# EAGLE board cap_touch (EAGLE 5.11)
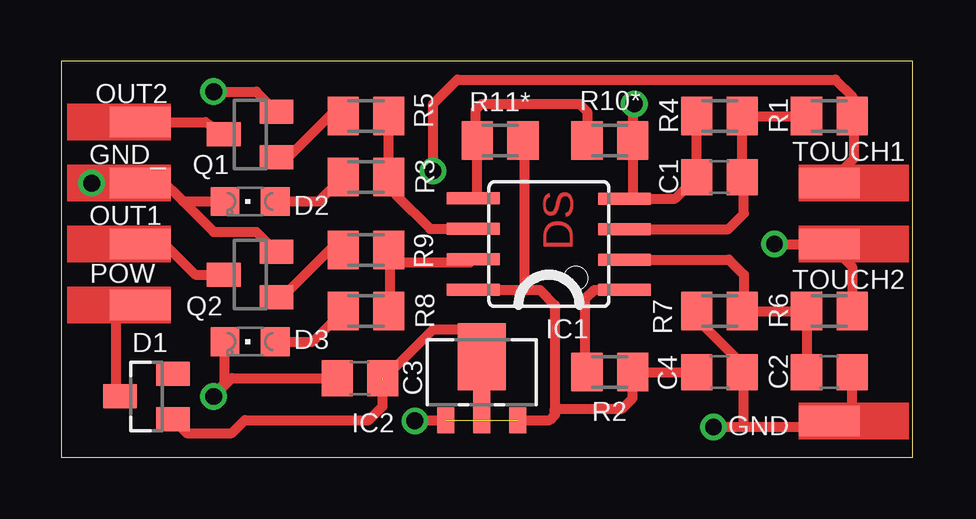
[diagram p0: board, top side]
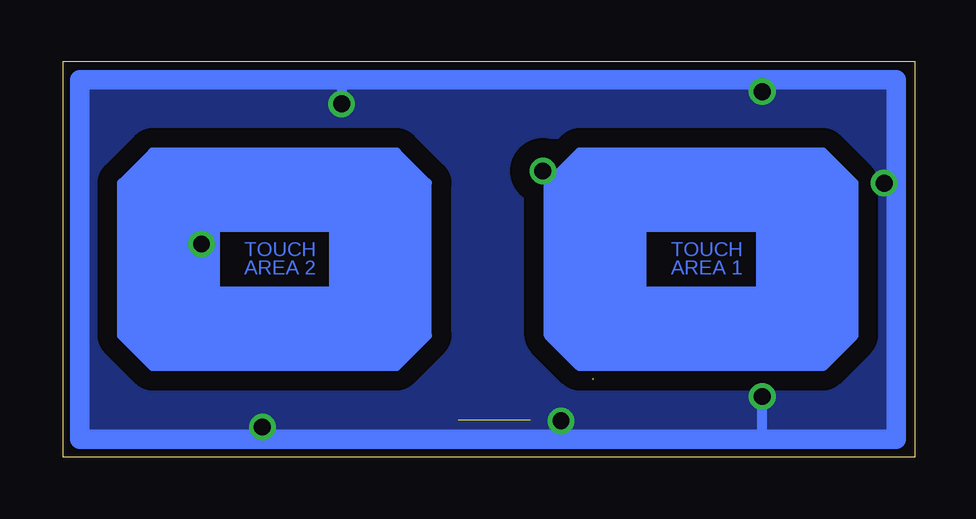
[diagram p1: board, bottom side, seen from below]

Size 35.48 x 16.5 mm. Coordinates in mm from the lower left corner, seen from the top.
Outline: 0,0 35.48,0 35.48,16.5 0,16.5 0,0
Copper layers (1*16): Top 0.035mm / dielectric 1.5mm / Bottom 0.035mm
Design rules "default": minimum track width 10mil, minimum drill 24mil, track to track 8mil, track to pad 8mil, pad to pad 8mil, via to via 8mil, smd to smd 8mil, copper to edge 40mil, drill to drill 8mil, minimum pad ring 10mil, minimum via ring 8mil, stop-mask expansion 4mil, vias tented up to drill 0mil, thermal gap 10mil

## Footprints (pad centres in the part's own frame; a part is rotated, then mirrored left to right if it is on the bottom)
C0805 = smd 1.3 x 1.5: 1 -0.95,0; 2 0.95,0
SOT23 = smd 1 x 1.4: 1 -0.95,-1.1; 2 0.95,-1.1; 3 0,1.1
CHIPLED_0805 = smd 1.2 x 1.2: A 0,-1.05; C 0,1.05
SMD1,27-2,54 = smd 1.27 x 2.54: 1 0,0
SOIC8 = smd 0.5 x 2.2: 1 -1.905,-3.154; 2 -0.645,-3.154; 3 0.625,-3.154; 4 1.895,-3.154; 5 1.905,3.154; 6 0.635,3.154; 7 -0.635,3.154; 8 -1.905,3.154
SOT89R = smd 0.7 x 1.1: 1 1.5,-1.75; 2 -1.5,-1.75 | smd 0.7 x 1.8: 3 0,-1.4 | smd 2 x 2.8: 4 0,0.9
M0805 = smd 1.3 x 1.6: 1 -0.95,0; 2 0.95,0

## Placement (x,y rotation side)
C1  22p  [C0805]  27.43,11.68 180 top
C2  22p  [C0805]  32,3.56 180 top
C3  100n  [C0805]  12.45,3.3 180 top
C4  100n  [C0805]  27.43,3.56 0 top
D1  [SOT23]  3.56,2.54 90 top
D2  [CHIPLED_0805]  7.87,10.67 90 top
D3  [CHIPLED_0805]  7.87,4.83 90 top
GND  [SMD1,27-2,54]  32,1.52 90 top
GND_  [SMD1,27-2,54]  3.3,11.43 90 top
IC1  ATTINY45  [SOIC8]  20.32,8.89 90 top
IC2  [SOT89R]  17.53,3.3 0 top
OUT1  [SMD1,27-2,54]  3.3,8.89 90 top
OUT2  [SMD1,27-2,54]  3.3,13.97 270 top
POW  [SMD1,27-2,54]  3.3,6.35 90 top
Q1  [SOT23]  7.87,13.46 90 top
Q2  [SOT23]  7.87,7.62 90 top
R1  4k7  [M0805]  32,14.22 180 top
R2  120k  [M0805]  22.86,3.56 0 top
R3  1k  [M0805]  12.7,14.22 180 top
R4  120k  [M0805]  27.43,14.22 180 top
R5  1k  [M0805]  12.7,11.68 0 top
R6  4k7  [M0805]  32,6.1 180 top
R7  120k  [M0805]  27.43,6.1 180 top
R8  1l  [M0805]  12.7,8.64 180 top
R9  1k  [M0805]  12.7,6.1 0 top
R10*  4k7  [M0805]  22.86,13.21 0 top
R11*  4k7  [M0805]  18.29,13.21 180 top
TOUCH1  [SMD1,27-2,54]  32,11.43 90 top
TOUCH2  [SMD1,27-2,54]  32,8.89 90 top

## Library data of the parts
C1-C4 R1-R9 R10* R11* = rcl
D1 = diode
D2 D3 = led
GND GND_ OUT1 OUT2 POW TOUCH1 TOUCH2 = wirepad
IC1 = avr-4
IC2 = v-reg
Q1 Q2 = transistor-small-signal

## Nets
CAP1: R6.1 TOUCH2.1
CAP2: R1.1 TOUCH1.1
GND: C1.2 C2.1 C3.2 C4.2 D2.C D3.C GND.1 GND_.1 IC1.4 IC2.1 IC2.2 Q1.2 Q2.2 R4.2 R7.2 R10*.2
N$1: Q1.1 R3.2
N$2: IC1.1 R2.1
N$3: Q2.1 R8.2
N$4: D2.A R5.1
N$5: C1.1 IC1.3 R1.2 R4.1
N$6: C2.2 IC1.2 R6.2 R7.1
N$10: D3.A R9.1
N$12: OUT1.1 Q2.3
N$14: IC1.5 R10*.1 R11*.2
N$15: D1.3 POW.1
N$16: OUT2.1 Q1.3
N$18: C3.1 D1.1 IC2.3
SO1: IC1.7 R8.1 R9.2
SO2: IC1.6 R3.1 R5.2
VCC: C4.1 IC1.8 R2.2 R11*.1

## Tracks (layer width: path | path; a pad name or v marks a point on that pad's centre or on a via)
CAP1  (via drill 0.7)
  Top 0.406: R6.1 32.95,7.94 TOUCH2.1 v29.72,8.89
  Bottom 0.406: 33.02,8.89 33.02,5.08 31.75,3.81 21.59,3.81 20.32,5.08 20.32,11.43 21.59,12.7 31.75,12.7 33.02,11.43 33.02,8.89 | 33.02,8.89 v29.72,8.89
CAP2  (via drill 0.7)
  Top 0.406: v15.49,11.94 15.49,14.73 16.51,15.75 32.26,15.75 32.95,15.05 R1.1 33.02,14.16 33.02,12.45 TOUCH1.1
  Bottom 0.406: 15.24,11.43 v15.49,11.94 | 15.24,11.43 13.97,12.7 3.81,12.7 2.54,11.43 2.54,5.08 3.81,3.81 13.97,3.81 15.24,5.08 15.24,11.43
GND  (via drill 0.7)  (1 unrouted)
  Top 0.406: R4.2 C1.2 25.58,10.79 IC1.4 23.81,10.87 R10*.2 23.81,14.67 v23.88,14.73 | C2.1 32.95,1.97 32.26,1.27 32,1.27 | 28.45,1.27 32,1.27 | R7.2 26.48,5.78 28.38,3.88 C4.2 28.45,3.49 28.45,1.27 | 32,1.27 GND.1 | Q2.2 8.96,8.57 8.13,9.4 6.35,9.4 5.08,10.67 | 5.08,10.67 4.06,11.68 3.56,11.68 GND_.1 v1.27,11.43 | 5.08,10.67 D2.C | C3.2 7.11,3.3 v6.35,2.54 6.82,3.08 D3.C | Q1.2 8.96,14.41 8.13,15.24 v6.35,15.24 | v27.18,1.27 28.45,1.27 | IC2.2 14.76,1.55 v14.73,1.52 | IC2.1 20.35,1.55 20.57,1.78 20.57,2.03
  Bottom 0.406: 0.76,11.43 v1.27,11.43 | 6.35,15.75 v6.35,15.24 | 27.18,0.76 v27.18,1.27 | 6.35,0.76 v6.35,2.54 | 23.88,15.75 v23.88,14.73 | 14.73,0.76 v14.73,1.52
  Bottom 0.813: 0.76,11.43 0.76,15.75 6.35,15.75 23.88,15.75 34.8,15.75 34.8,0.76 27.18,0.76 14.73,0.76 6.35,0.76 0.76,0.76 0.76,11.43
  pour Bottom (isolate 0.813, no thermals): 0.51,16 34.8,16 34.8,0.51 0.51,0.51
N$1
  Top 0.406: R3.2 11.18,14.22 9.4,12.45 9.04,12.45 Q1.1
N$2
  Top 0.406: IC1.1 22.23,6.99 21.84,6.6 21.84,3.62 R2.1
N$3
  Top 0.406: R8.2 11.18,8.64 9.21,6.67 Q2.1
N$4
  Top 0.406: R5.1 10.73,10.67 D2.A
N$5
  Top 0.406: IC1.3 27.8,9.52 28.45,10.16 28.45,11.18 | 28.45,11.18 28.45,11.62 C1.1 | 28.45,11.18 28.38,11.24 R4.1 R1.2
N$6
  Top 0.406: IC1.2 27.82,8.25 28.45,7.62 28.45,6.16 R7.1 R6.2 C2.2
N$7
  Bottom 0.406: 3.81,12.45 3.81,11.43 2.79,11.43 3.56,12.19 3.56,11.68 3.3,11.68
N$8
  Bottom 0.406: 2.79,5.08 3.81,5.08 3.81,4.06 3.05,4.83 3.56,4.83 3.56,4.57
N$9
  Bottom 0.406: 14.99,11.43 13.97,11.43 13.97,12.45 14.73,11.68 14.22,11.68 14.22,11.94
N$10
  Top 0.406: R9.1 10.48,4.83 D3.A
N$11
  Bottom 0.406: 13.97,4.06 13.97,5.08 14.99,5.08 14.22,4.32 14.22,4.83 14.48,4.83
N$12
  Top 0.406: OUT1.1 4.32,8.89 5.59,7.62 Q2.3
N$14
  Top 0.406: R10*.1 21.91,14.41 21.59,14.73 17.53,14.73 17.27,14.48 17.27,13.53 R11*.2 17.34,10.97 IC1.5
N$15
  Top 0.406: POW.1 2.29,6.35 2.29,2.96 D1.3
N$16
  Top 0.406: OUT2.1 6.01,13.97 Q1.3
N$17
  Bottom 0.406: 21.59,12.45 21.59,11.43 20.57,11.43 21.34,12.19 21.34,11.68 21.08,11.68
N$18  (1 unrouted)
  Top 0.406: 4.95,1.55 D1.1 5.23,1.02 7.11,1.02 7.65,1.55 12.82,1.55 13.4,2.13 13.4,3.24 15.49,5.33 17.53,5.33 IC2.3
N$20
  Bottom 0.406: 32.77,11.43 31.75,11.43 31.75,12.45 32.51,11.68 32,11.68 32,11.94
N$21
  Bottom 0.406: 31.75,4.06 31.75,5.08 32.77,5.08 32,4.32 32,4.83 32.26,4.83
N$22
  Bottom 0.406: 20.57,5.08 21.59,5.08 21.59,4.06 20.83,4.83 21.34,4.83 21.34,4.57
SO1
  Top 0.406: IC1.7 17.04,8.13 13.72,8.13 | 13.72,8.13 13.65,8.19 R8.1 | R9.2 13.72,6.16 13.72,8.13
SO2
  Top 0.406: R3.1 R5.2 13.97,11.36 13.97,10.92 15.37,9.52 IC1.6
VCC
  Top 0.406: C4.1 R2.2 23.81,2.47 23.37,2.03 20.57,2.03 20.57,6.35 19.94,6.99 19.3,6.99 | 19.3,6.99 IC1.8 17.4,6.99 | R11*.1 19.24,13.78 19.3,13.72 19.3,6.99
(copper drawn outside any net)
  shapes: Bottom area x8, Top area x7

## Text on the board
Top: DS
Bottom: TOUCH | TOUCH | AREA 1 | AREA 2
